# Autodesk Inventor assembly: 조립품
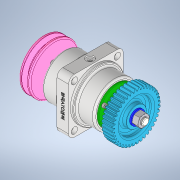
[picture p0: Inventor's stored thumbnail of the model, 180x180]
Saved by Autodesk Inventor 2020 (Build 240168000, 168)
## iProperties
Created: 2023-10
Part Number: 조립품
Document SubType Name: Assembly
Designer: oem
Author: oem
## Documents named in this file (12)
- C:\Users\oem\Desktop\731006V1012\조립품.iam
- C:\Users\oem\Desktop\731006V1012\본체.ipt
- C:\Users\oem\Desktop\731006V1012\V벨트풀리.ipt
- C:\Users\oem\Desktop\731006V1012\너트 M12x1.25.ipt
- C:\Users\oem\Desktop\731006V1012\베어링 6204.ipt
- C:\Users\oem\Desktop\731006V1012\볼트 M4x0.7.ipt
- C:\Users\oem\Desktop\731006V1012\스퍼기어.ipt
- C:\Users\oem\Desktop\731006V1012\오일실 20x35x8.ipt
- C:\Users\oem\Desktop\731006V1012\와셔 12x24.ipt
- C:\Users\oem\Desktop\731006V1012\축.ipt
- C:\Users\oem\Desktop\731006V1012\커버.ipt
- C:\Users\oem\Desktop\731006V1012\키 5x5.ipt
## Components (1 placed, 1 different names)
1. V벨트풀리:1 — 각도:2
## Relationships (1: Angle 1)
- 각도:2 [Angle]: V벨트풀리:1
